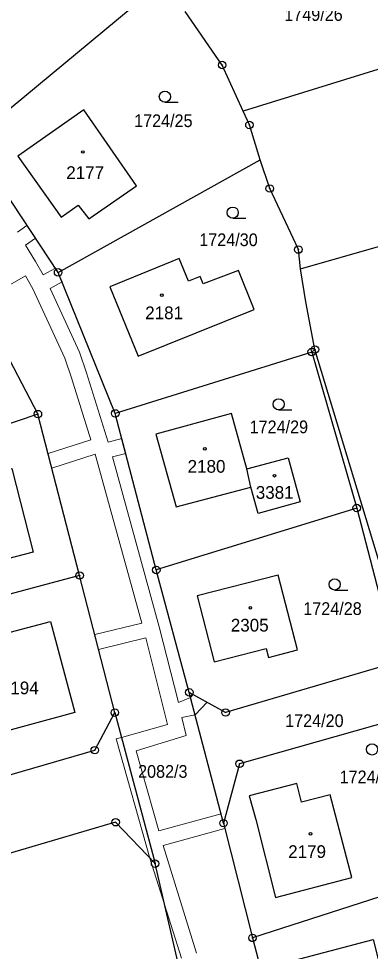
# Model space of a CAD drawing. Extents: x -679733 to -673243, y -1075091 to -1066557.
# Drawn here: x -676657.5 to -676610.5, y -1072173.4 to -1072048.7 of the extents above; entities that cross this region are included whole.
import ezdxf

# ---------------------------------------------------------------- set-up
doc = ezdxf.new("R2010")
doc.units = 0
doc.header["$LTSCALE"] = 0.68
for name, color, linetype, lineweight in [('1', 7, 'Continuous', 25), ('13', 7, 'Continuous', 13), ('3', 7, 'Continuous', 25), ('5', 7, 'Continuous', 25), ('8', 7, 'Continuous', 25)]:
    doc.layers.add(name, color=color, linetype=linetype, lineweight=lineweight)
doc.layers.add('2', color=7, linetype='Continuous')

msp = doc.modelspace()

# ---------------------------------------------------------------- linework, layer by layer
at = {"layer": '1'}
for p, q in [((-676664.27, -1072065.35), (-676639.08, -1072044.43)), ((-676600.93, -1072052.86), (-676627.53, -1072061.09)), ((-676652.26, -1072082.65), (-676625.25, -1072067.62)), ((-676666.13, -1072080.35), (-676654.96, -1072101.6)), ((-676618.37, -1072093.31), (-676644.62, -1072101.51)), ((-676654.96, -1072101.6), (-676685.71, -1072112.07)), ((-676649.38, -1072123.18), (-676654.96, -1072101.6)), ((-676626.49, -1072111.38), (-676627.04, -1072108.94)), ((-676612.35, -1072114.16), (-676639.14, -1072122.45)), ((-676644.68, -1072141.52), (-676639.3, -1072161.72)), ((-676630.15, -1072156.31), (-676626.28, -1072171.65))]:
    msp.add_line(p, q, dxfattribs=at)
for points in [[(-676627.53, -1072061.09), (-676630.33, -1072054.92), (-676635.3, -1072047.75)], [(-676625.25, -1072067.62), (-676626.69, -1072062.94), (-676627.53, -1072061.09)], [(-676630.15, -1072156.31), (-676634.73, -1072138.81), (-676639.14, -1072122.45), (-676644.62, -1072101.51), (-676652.26, -1072082.65), (-676662.02, -1072067.93)], [(-676619.88, -1072082.19), (-676620.15, -1072079.6), (-676623.98, -1072071.44), (-676625.25, -1072067.62)], [(-676619.88, -1072082.19), (-676602.27, -1072077.16), (-676584.82, -1072071.93)], [(-676617.93, -1072092.96), (-676619.14, -1072086.6), (-676619.88, -1072082.19)], [(-676627.04, -1072108.94), (-676629.07, -1072101.52), (-676639.19, -1072104.29), (-676636.48, -1072114.02), (-676626.49, -1072111.38)], [(-676627.04, -1072108.94), (-676621.51, -1072107.43), (-676619.89, -1072113.34), (-676625.53, -1072114.9), (-676626.49, -1072111.38)], [(-676644.68, -1072141.52), (-676649.38, -1072123.18), (-676682.57, -1072132.06), (-676673.32, -1072154.08)], [(-676607.01, -1072134.77), (-676629.87, -1072141.5), (-676634.73, -1072138.81)], [(-676673.32, -1072154.08), (-676647.36, -1072146.54), (-676644.68, -1072141.52)], [(-676604.91, -1072141.8), (-676628, -1072148.36), (-676630.15, -1072156.31)], [(-676639.3, -1072161.72), (-676644.57, -1072156.18), (-676699.67, -1072172.4), (-676701.82, -1072178.86)], [(-676701.82, -1072178.86), (-676699.46, -1072187.24), (-676698.22, -1072191.63), (-676696.78, -1072196.76), (-676666.08, -1072187.75), (-676635.37, -1072178.74), (-676639.3, -1072161.72)], [(-676600.13, -1072163.22), (-676626.28, -1072171.65), (-676621.19, -1072191.08), (-676595.53, -1072182.68)]]:
    msp.add_lwpolyline(points, dxfattribs=at)
for points in [[(-676651.87, -1072075.27), (-676649.58, -1072073.64), (-676648.14, -1072075.51), (-676641.77, -1072071.06), (-676648.82, -1072060.91), (-676657.63, -1072067.09)], [(-676633.27, -1072083.18), (-676634.85, -1072083.83), (-676636.08, -1072080.81), (-676645.34, -1072084.58), (-676641.57, -1072093.86), (-676626.06, -1072087.6), (-676628.17, -1072082.38), (-676632.86, -1072084.2)], [(-676612.35, -1072114.16), (-676607.01, -1072134.77), (-676605.41, -1072134.3), (-676617.93, -1072092.96), (-676618.37, -1072093.31)], [(-676658.46, -1072108.87), (-676655.61, -1072120.08), (-676663.72, -1072122.14), (-676666.73, -1072110.97)], [(-676622.86, -1072123.12), (-676633.66, -1072125.89), (-676631.39, -1072134.75), (-676624.46, -1072132.96), (-676624.16, -1072134.14), (-676620.28, -1072133.14)], [(-676650.02, -1072141.5), (-676662.2, -1072144.79), (-676665.46, -1072132.56), (-676653.29, -1072129.32)], [(-676625.84, -1072155.82), (-676623.21, -1072166.23), (-676612.99, -1072163.56), (-676615.89, -1072152.5), (-676619.71, -1072153.5), (-676620.37, -1072150.99), (-676626.72, -1072152.67)], [(-676618.25, -1072184.77), (-676620.81, -1072174.69), (-676610.17, -1072171.88), (-676607.61, -1072181.99)]]:
    msp.add_lwpolyline(points, close=True, dxfattribs=at)
at = {"layer": '13'}
for points in [[(-676633.75, -1072173.68), (-676638.24, -1072159.3), (-676629.97, -1072157.04), (-676630.15, -1072156.31), (-676630.48, -1072155.06), (-676638.82, -1072157.34), (-676641.83, -1072146.63), (-676635.16, -1072144.57), (-676635.71, -1072142.16), (-676633.94, -1072141.84), (-676632.35, -1072140.13), (-676634.19, -1072139.11), (-676634.55, -1072139.5), (-676636.19, -1072140.17), (-676638.74, -1072130.03), (-676645, -1072107.31), (-676643.22, -1072106.85), (-676643.74, -1072104.88), (-676645.58, -1072105.35), (-676648.46, -1072096.09), (-676649.4, -1072093.33), (-676653.34, -1072084.79), (-676651.74, -1072083.93), (-676652.26, -1072082.65), (-676652.63, -1072082.09), (-676654.27, -1072082.97), (-676655.28, -1072081.18), (-676656.62, -1072079.01), (-676655.29, -1072078.08), (-676656.42, -1072076.37), (-676657.69, -1072077.27)], [(-676662.82, -1072086.65), (-676656.61, -1072083.13), (-676655.64, -1072084.84), (-676651.38, -1072094.11), (-676650.48, -1072096.75), (-676647.9, -1072105.04), (-676653.6, -1072106.86), (-676653.09, -1072108.85), (-676647.29, -1072106.98), (-676641.07, -1072129.57), (-676647.36, -1072131.08), (-676646.85, -1072133.06), (-676640.55, -1072131.54), (-676637.66, -1072143.13), (-676643.8, -1072144.84), (-676644.51, -1072145.01), (-676640, -1072160.99), (-676638.04, -1072167.17), (-676635.77, -1072174.34)]]:
    msp.add_lwpolyline(points, dxfattribs=at)
at = {"layer": '3'}
for p, q in [((-676637.983, -1072059.9), (-676636.233, -1072059.9)), ((-676628.923, -1072075.41), (-676627.173, -1072075.41)), ((-676622.783, -1072101.04), (-676621.033, -1072101.04)), ((-676615.293, -1072125.13), (-676613.543, -1072125.13))]:
    msp.add_line(p, q, dxfattribs=at)
for centre in [(-676637.9829, -1072059.1498), (-676628.9229, -1072074.6598), (-676622.7829, -1072100.2898), (-676615.2929, -1072124.3798), (-676610.2929, -1072146.4498)]:
    msp.add_circle(centre, 0.75, dxfattribs=at)
at = {"layer": '5'}
for centre in [(-676648.9568, -1072066.5492), (-676638.3968, -1072085.6892), (-676632.6568, -1072106.2392), (-676623.3368, -1072109.8392), (-676626.5668, -1072127.4992), (-676618.5268, -1072157.7392)]:
    msp.add_circle(centre, 0.175, dxfattribs=at)
at = {"layer": '8'}
for centre, radius in [((-676630.33, -1072054.9199), 0.5), ((-676630.33, -1072054.9199), 0.0303), ((-676626.69, -1072062.9399), 0.5), ((-676626.69, -1072062.9399), 0.0303), ((-676623.98, -1072071.4399), 0.5), ((-676623.98, -1072071.4399), 0.0303), ((-676620.15, -1072079.5999), 0.5), ((-676620.15, -1072079.5999), 0.0303), ((-676652.26, -1072082.6499), 0.5), ((-676652.26, -1072082.6499), 0.0303), ((-676618.37, -1072093.3099), 0.5), ((-676617.93, -1072092.9599), 0.5), ((-676618.37, -1072093.3099), 0.0303), ((-676617.93, -1072092.9599), 0.0303), ((-676654.96, -1072101.5999), 0.5), ((-676654.96, -1072101.5999), 0.0303), ((-676644.62, -1072101.5099), 0.5), ((-676644.62, -1072101.5099), 0.0303), ((-676612.35, -1072114.1599), 0.5), ((-676612.35, -1072114.1599), 0.0303), ((-676639.14, -1072122.4499), 0.5), ((-676649.38, -1072123.1799), 0.5), ((-676649.38, -1072123.1799), 0.0303), ((-676639.14, -1072122.4499), 0.0303), ((-676634.73, -1072138.8099), 0.5), ((-676634.73, -1072138.8099), 0.0303), ((-676644.68, -1072141.5199), 0.5), ((-676644.68, -1072141.5199), 0.0303), ((-676629.87, -1072141.4999), 0.5), ((-676629.87, -1072141.4999), 0.0303), ((-676647.36, -1072146.5399), 0.5), ((-676647.36, -1072146.5399), 0.0303), ((-676628, -1072148.3599), 0.5), ((-676628, -1072148.3599), 0.0303), ((-676644.57, -1072156.1799), 0.5), ((-676644.57, -1072156.1799), 0.0303), ((-676630.15, -1072156.3099), 0.5), ((-676630.15, -1072156.3099), 0.0303), ((-676639.3, -1072161.7199), 0.5), ((-676639.3, -1072161.7199), 0.0303), ((-676626.28, -1072171.6499), 0.5), ((-676626.28, -1072171.6499), 0.0303)]:
    msp.add_circle(centre, radius, dxfattribs=at)

# ---------------------------------------------------------------- texts
at = {"layer": '2', "width": 0.95}
for s, p in [('1749/26', (-676622.03, -1072049.019)), ('1724/25', (-676642.1, -1072063.22)), ('1724/30', (-676633.39, -1072079.14)), ('1724/29', (-676626.66, -1072104.16)), ('1724/28', (-676619.49, -1072128.46)), ('1724/20', (-676621.91, -1072143.45)), ('2082/3', (-676641.57, -1072150.239)), ('1724/27', (-676614.63, -1072150.97))]:
    msp.add_text(s, height=1.7, dxfattribs=at).set_placement(p)
at = {"layer": '2'}
for s, p in [('2177', (-676651.17, -1072070.16)), ('2181', (-676640.62, -1072088.91)), ('2180', (-676634.95, -1072109.44)), ('3381', (-676625.84, -1072112.93)), ('2305', (-676629.18, -1072130.68)), ('2194', (-676659.91, -1072139.07)), ('2179', (-676621.51, -1072160.96))]:
    msp.add_text(s, height=1.7, dxfattribs=at).set_placement(p)

doc.saveas('drawing.dxf')
